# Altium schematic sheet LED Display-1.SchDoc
size A4
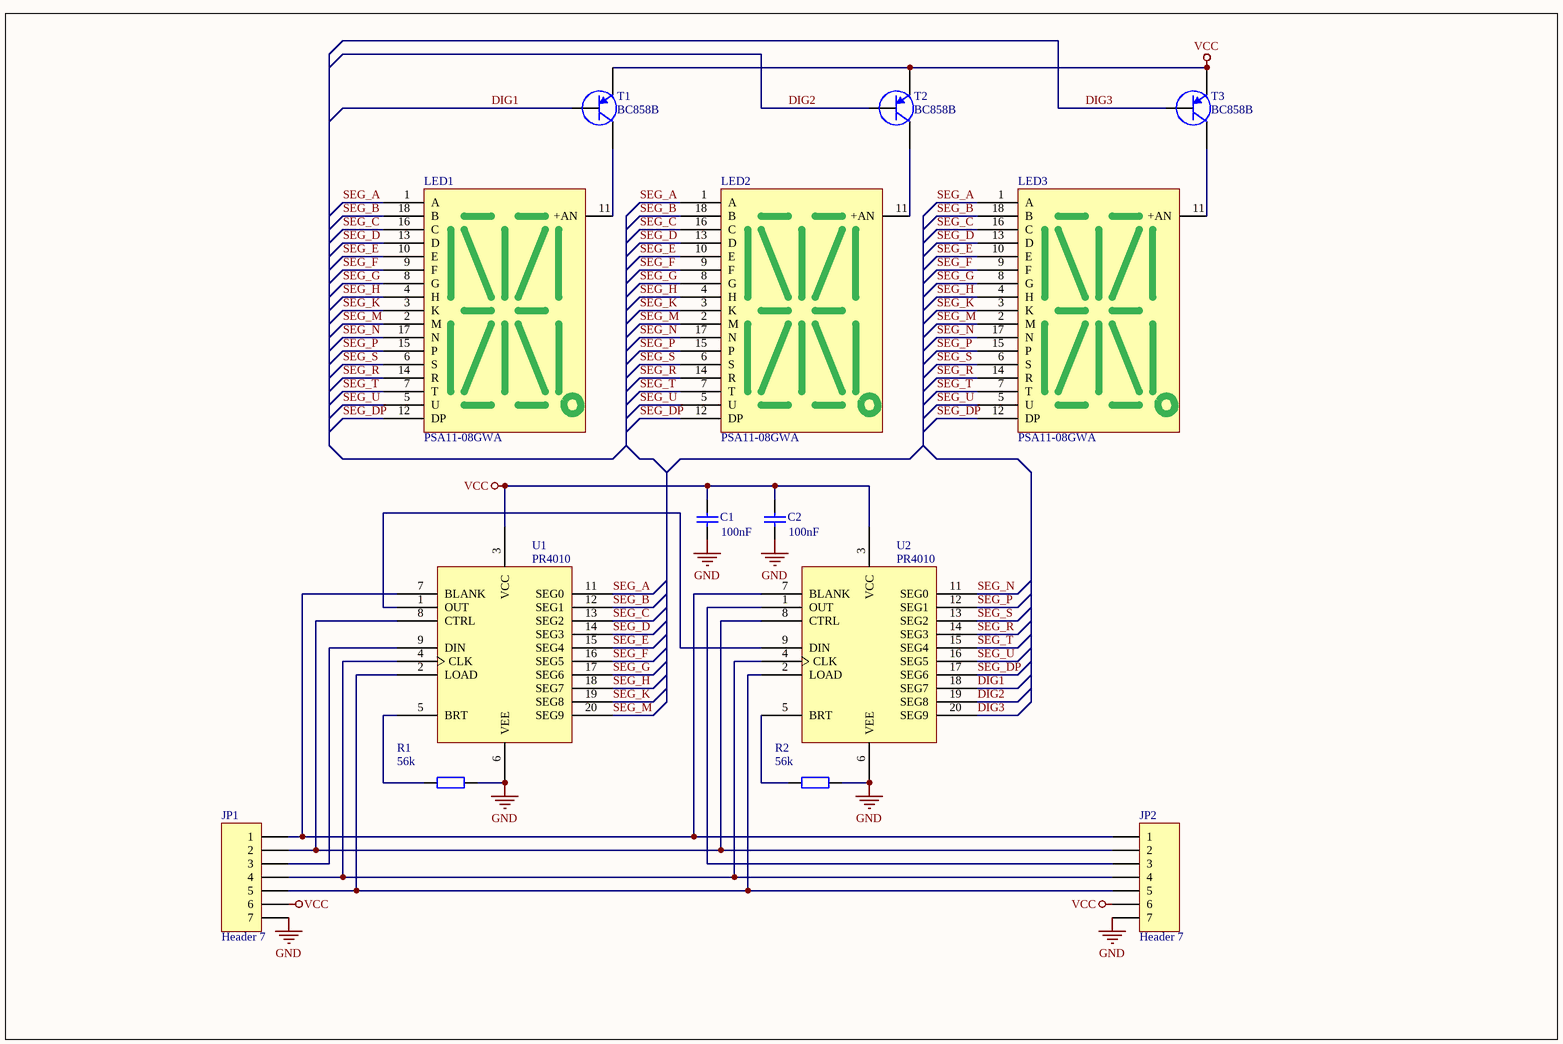
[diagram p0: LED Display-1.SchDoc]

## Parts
C1  value 100nF  [1206]  (hidden comment: Cap)
C2  value 100nF  [1206]  (hidden comment: Cap)
JP1  Header 7  [ZLACZE-K7]
JP2  Header 7  [ZLACZE-K7]
LED1  PSA11-08GWA
LED2  PSA11-08GWA
LED3  PSA11-08GWA
R1  value 56k  [1206]  (hidden comment: Res2)
R2  value 56k  [1206]  (hidden comment: Res2)
T1  BC858B  [SOT95P240-3N]
T2  BC858B  [SOT95P240-3N]
T3  BC858B  [SOT95P240-3N]
U1  PR4010  [SSOP20]
U2  PR4010  [SSOP20]

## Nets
GND: C1.1 C2.1 JP1.7 JP2.7 R1.2 R2.2 U1.6(VEE) U2.6(VEE)
VCC: C1.2 C2.2 JP1.6 JP2.6 T1.2(E) T2.2(E) T3.2(E) U1.3(VCC) U2.3(VCC)
DIG1: T1.1(B) U2.18(SEG7)
DIG2: T2.1(B) U2.19(SEG8)
DIG3: T3.1(B) U2.20(SEG9)
SEG_A: LED1.1(A) LED2.1(A) LED3.1(A) U1.11(SEG0)
SEG_B: LED1.18(B) LED2.18(B) LED3.18(B) U1.12(SEG1)
SEG_C: LED1.16(C) LED2.16(C) LED3.16(C) U1.13(SEG2)
SEG_D: LED1.13(D) LED2.13(D) LED3.13(D) U1.14(SEG3)
SEG_DP: LED1.12(DP) LED2.12(DP) LED3.12(DP) U2.17(SEG6)
SEG_E: LED1.10(E) LED2.10(E) LED3.10(E) U1.15(SEG4)
SEG_F: LED1.9(F) LED2.9(F) LED3.9(F) U1.16(SEG5)
SEG_G: LED1.8(G) LED2.8(G) LED3.8(G) U1.17(SEG6)
SEG_H: LED1.4(H) LED2.4(H) LED3.4(H) U1.18(SEG7)
SEG_K: LED1.3(K) LED2.3(K) LED3.3(K) U1.19(SEG8)
SEG_M: LED1.2(M) LED2.2(M) LED3.2(M) U1.20(SEG9)
SEG_N: LED1.17(N) LED2.17(N) LED3.17(N) U2.11(SEG0)
SEG_P: LED1.15(P) LED2.15(P) LED3.15(P) U2.12(SEG1)
SEG_R: LED1.14(R) LED2.14(R) LED3.14(R) U2.14(SEG3)
SEG_S: LED1.6(S) LED2.6(S) LED3.6(S) U2.13(SEG2)
SEG_T: LED1.7(T) LED2.7(T) LED3.7(T) U2.15(SEG4)
SEG_U: LED1.5(U) LED2.5(U) LED3.5(U) U2.16(SEG5)
NetJP1_1: JP1.1 JP2.1 U1.7(BLANK) U2.7(BLANK)
NetJP1_2: JP1.2 JP2.2 U1.8(CTRL) U2.8(CTRL)
NetJP1_3: JP1.3 U1.9(DIN)
NetJP1_4: JP1.4 JP2.4 U1.4(CLK) U2.4(CLK)
NetJP1_5: JP1.5 JP2.5 U1.2(LOAD) U2.2(LOAD)
NetJP2_3: JP2.3 U2.1(OUT)
NetLED1_11: LED1.11(+AN) T1.3(C)
NetLED2_11: LED2.11(+AN) T2.3(C)
NetLED3_11: LED3.11(+AN) T3.3(C)
NetR1_1: R1.1 U1.5(BRT)
NetR2_1: R2.1 U2.5(BRT)
NetU1_1: U1.1(OUT) U2.9(DIN)

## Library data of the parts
C1 C2 = Cap: Capacitor
JP1 JP2 = Header 7: Header, 7-Pin
R1 R2 = Res2: Resistor
T1-T3 = PNP: PNP Bipolar Transistor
